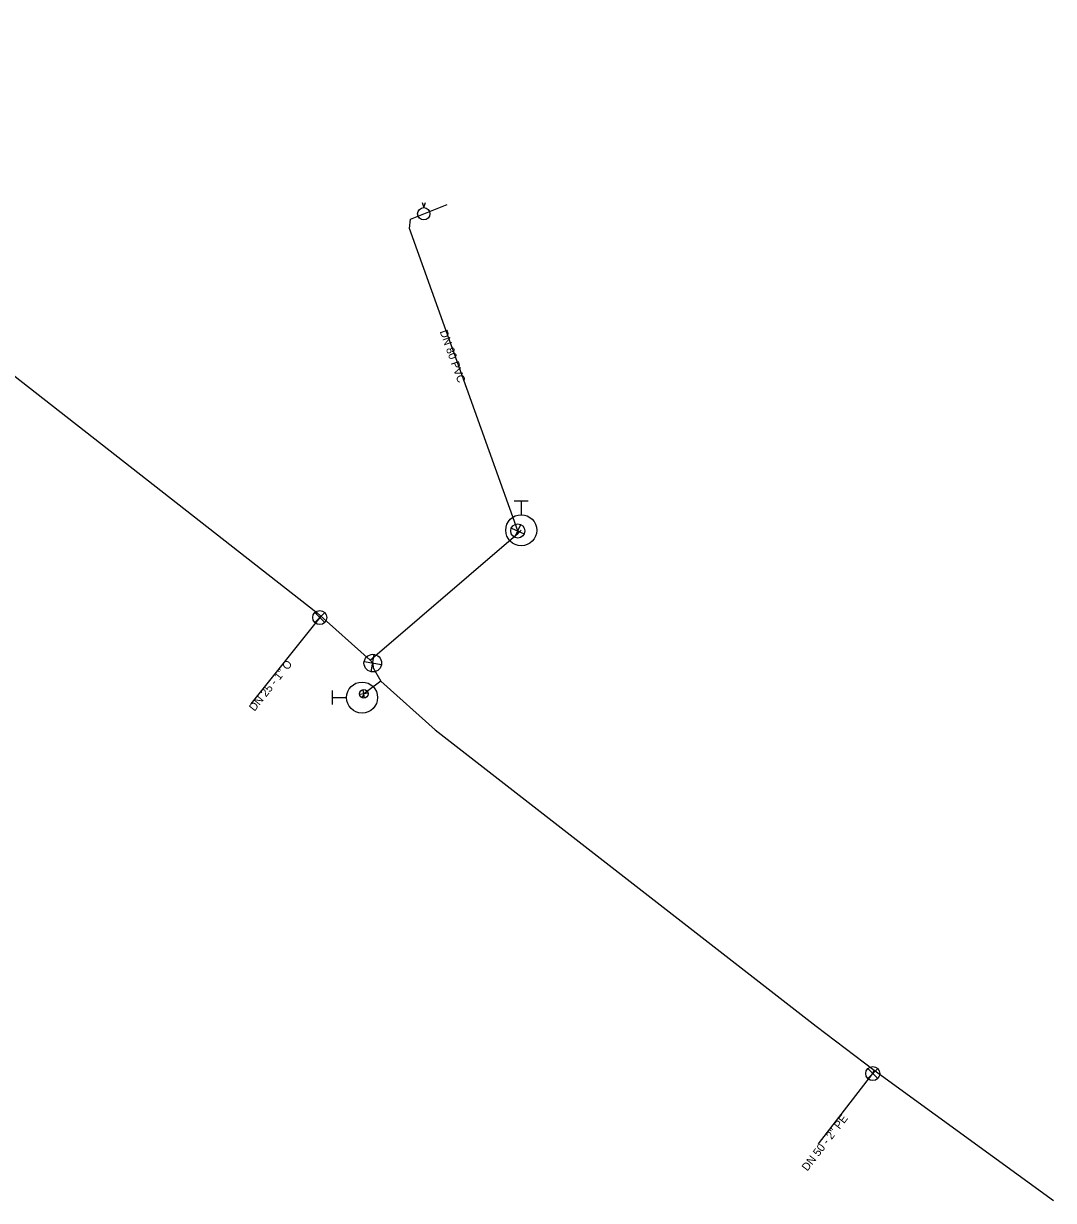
# Model space of a CAD drawing. Extents: x -492321 to -492053, y -1126159 to -1125902.
# Drawn here: x -492111.6 to -492053, y -1126036.1 to -1125969.2 of the extents above; entities that cross this region are included whole.
import ezdxf

# ---------------------------------------------------------------- set-up
doc = ezdxf.new("R2010")
doc.units = 0
for name, color, linetype in [('_hydrantova_odbocka_', 7, 'Continuous'), ('_pripojka_prevzato_z_dokumentace_', 7, 'Continuous'), ('_pripojka_priblizne_', 7, 'Continuous'), ('_voda_smvak_prevzato_z_dokumentace_', 7, 'Continuous'), ('Default', 7, 'Continuous'), ('MoLevel 27', 7, 'Continuous'), ('MoLevel 28', 7, 'Continuous'), ('MoLevel 30', 7, 'Continuous'), ('MoLevel 32', 7, 'Continuous'), ('MoLevel 53', 7, 'Continuous'), ('MoLevel 55', 7, 'Continuous')]:
    doc.layers.add(name, color=color, linetype=linetype)

# ---------------------------------------------------------------- blocks, each defined once
blk = doc.blocks.new('_uzaver_')
at = {"layer": 'Default'}
for p, q in [((-0.000035, -0.000035), (0.000035, 0.000035)), ((0.000035, -0.000035), (-0.000035, 0.000035))]:
    blk.add_line(p, q, dxfattribs=at)
for radius in [0.00005, 0.0000025]:
    blk.add_circle((0, 0), radius, dxfattribs=at)
blk = doc.blocks.new('_uzaver_pripojka_')
at = {"layer": 'Default'}
for p, q in [((-0.000035, -0.000035), (0.000035, 0.000035)), ((0.000035, -0.000035), (-0.000035, 0.000035))]:
    blk.add_line(p, q, dxfattribs=at)
for radius in [0.00005, 0.0000025]:
    blk.add_circle((0, 0), radius, dxfattribs=at)
blk = doc.blocks.new('_hydrant_voda_')
at = {"layer": 'Default'}
for p, q in [((-0.0000225, 0.000095), (0.0000225, 0.000095)), ((0, 0.000095), (0, 0.00005))]:
    blk.add_line(p, q, dxfattribs=at)
blk.add_circle((0, 0), 0.00005, dxfattribs=at)
blk = doc.blocks.new('_sachta_voda_')
at = {"layer": 'Default'}
blk.add_lwpolyline([(-0.00001, 0.000065), (0, 0.000035), (0.00001, 0.000065)], dxfattribs=at)
blk.add_circle((0, 0), 0.000035, dxfattribs=at)

msp = doc.modelspace()

# ---------------------------------------------------------------- linework, layer by layer
at = {"layer": '_hydrantova_odbocka_'}
msp.add_lwpolyline([(-492091.25, -1126006.57), (-492092.22, -1126007.29), (-492092.32, -1126007.5)], dxfattribs=at)
at = {"layer": '_pripojka_prevzato_z_dokumentace_'}
msp.add_line((-492088.812, -1125980), (-492087.478, -1125979.466), dxfattribs=at)
for points in [[(-492083.446, -1125998.156), (-492083.47, -1125998.03), (-492089.62, -1125980.839), (-492089.569, -1125980.304), (-492088.812, -1125980)], [(-492094.69, -1126002.843), (-492094.72, -1126002.95), (-492098.644, -1126007.857)]]:
    msp.add_lwpolyline(points, dxfattribs=at)
at = {"layer": '_pripojka_priblizne_'}
msp.add_lwpolyline([(-492066.38, -1126032.87), (-492063.3, -1126028.87), (-492063.22, -1126028.68)], dxfattribs=at)
at = {"layer": '_voda_smvak_prevzato_z_dokumentace_'}
msp.add_line((-492091.849, -1126005.375), (-492091.709, -1126005.541), dxfattribs=at)
for points in [[(-492170.066, -1125944.617), (-492136.347, -1125970.233), (-492094.876, -1126002.677), (-492091.849, -1126005.375)], [(-492091.849, -1126005.375), (-492083.446, -1125998.156), (-492083.272, -1125997.99)], [(-492091.709, -1126005.541), (-492091.68, -1126005.8), (-492091.25, -1126006.57), (-492088.17, -1126009.326), (-492066.51, -1126026.17), (-492063.22, -1126028.68), (-492053.037, -1126036.084)]]:
    msp.add_lwpolyline(points, dxfattribs=at)

# ---------------------------------------------------------------- block references
at = {"layer": 'MoLevel 27'}
for p, xscale, yscale, rotation in [((-492091.709, -1126005.541), 9999.999999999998, 10000.000000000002, -55.19027222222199), ((-492092.22, -1126007.29), 5000, 5000, 53.816875)]:
    msp.add_blockref('_uzaver_', p, dxfattribs=dict(at, xscale=xscale, yscale=yscale, rotation=rotation))
at = {"layer": 'MoLevel 28', "xscale": 17636.68430335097, "yscale": 17636.68430335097}
msp.add_blockref('_hydrant_voda_', (-492083.272, -1125997.99), dxfattribs=at)
at = {"layer": 'MoLevel 28', "xscale": 17636.68430335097, "yscale": 17636.68430335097, "rotation": 90}
msp.add_blockref('_hydrant_voda_', (-492092.32, -1126007.5), dxfattribs=at)
at = {"layer": 'MoLevel 30', "xscale": 10000, "yscale": 10000}
msp.add_blockref('_sachta_voda_', (-492088.811, -1125980.001), dxfattribs=at)
at = {"layer": 'MoLevel 53', "xscale": 8000, "yscale": 8000, "rotation": -69.675658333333}
msp.add_blockref('_uzaver_pripojka_', (-492083.47, -1125998.03), dxfattribs=at)
at = {"layer": 'MoLevel 53', "xscale": 7999.999999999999, "yscale": 7999.999999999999}
for p in [(-492094.72, -1126002.95), (-492063.3, -1126028.87)]:
    msp.add_blockref('_uzaver_pripojka_', p, dxfattribs=at)

# ---------------------------------------------------------------- texts
at = {"layer": 'MoLevel 32'}
msp.add_text("DN 50 - 2'' PE", height=0.455, rotation=52.40373, dxfattribs=at).set_placement((-492067.021, -1126034.448))
at = {"layer": 'MoLevel 55'}
for s, rotation, p in [('DN 80 PVC', 289.68444, (-492087.913, -1125986.695)), ("DN 25 - 1'' O", 51.35087, (-492098.428, -1126008.315))]:
    msp.add_text(s, height=0.455, rotation=rotation, dxfattribs=at).set_placement(p)

doc.saveas('drawing.dxf')
